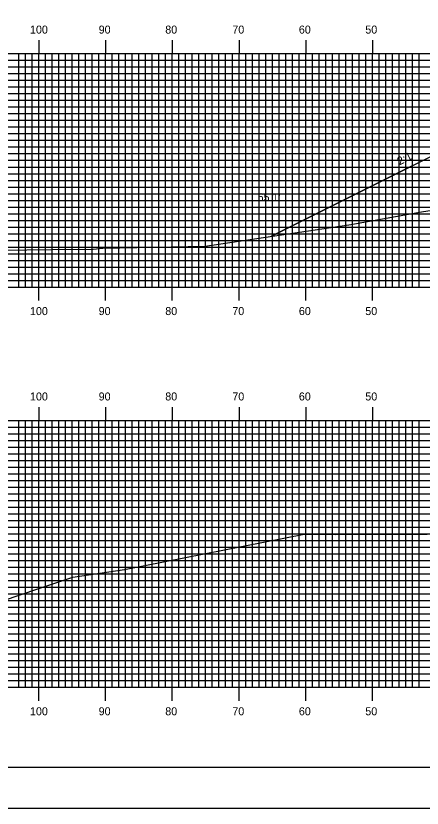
# Model space of a CAD drawing. Extents: x 1755888 to 1756232, y 442591 to 442811.
# Drawn here: x 1755950.6 to 1756011.5, y 442590.5 to 442709.3 of the extents above; entities that cross this region are included whole.
import ezdxf

# ---------------------------------------------------------------- set-up
doc = ezdxf.new("R2010")
doc.units = 0
for name, color, linetype in [('ANNOTATION', 7, 'Continuous'), ('BORDER', 7, 'Continuous'), ('D_Roadway_Centerline', 7, 'Continuous'), ('D_Roadway_SlopeLines', 7, 'Continuous'), ('D_Text_Standard', 7, 'Continuous'), ('H_V ANNOTATION', 7, 'Continuous'), ('MAJOR', 7, 'Continuous'), ('MINOR', 7, 'Continuous'), ('PLOT BOUNDARY', 7, 'Continuous'), ('S_Roadway_Centerline', 7, 'Continuous')]:
    doc.layers.add(name, color=color, linetype=linetype)

msp = doc.modelspace()

# ---------------------------------------------------------------- linework, layer by layer
at = {"layer": 'BORDER'}
msp.add_lwpolyline([(1755904.46, 442596.67), (1756224.46, 442596.67), (1756224.46, 442806.67), (1755904.46, 442806.67)], close=True, dxfattribs=at)
at = {"layer": 'D_Roadway_Centerline'}
msp.add_lwpolyline([(1755988.92, 442676.28), (1756026.31, 442694.97), (1756031.06, 442697.35), (1756034.06, 442697.47), (1756042.06, 442697.79), (1756054.06, 442698.03), (1756066.06, 442697.79), (1756078.06, 442697.31), (1756093.72, 442696.69), (1756103.15, 442694.07), (1756119.31, 442689.58)], dxfattribs=at)
at = {"layer": 'D_Roadway_SlopeLines'}
msp.add_lwpolyline([(1756031.06, 442697.35), (1755988.92, 442676.28)], dxfattribs=at)
at = {"layer": 'MAJOR'}
for p, q in [((1755954.06, 442705.67), (1755954.06, 442703.67)), ((1755964.06, 442705.67), (1755964.06, 442703.67)), ((1755974.06, 442705.67), (1755974.06, 442703.67)), ((1755984.06, 442705.67), (1755984.06, 442703.67)), ((1755994.06, 442705.67), (1755994.06, 442703.67)), ((1756004.06, 442705.67), (1756004.06, 442703.67)), ((1755914.06, 442703.67), (1756194.06, 442703.67)), ((1755914.06, 442703.67), (1756194.06, 442703.67)), ((1755954.06, 442668.67), (1755954.06, 442703.67)), ((1755964.06, 442668.67), (1755964.06, 442703.67)), ((1755974.06, 442668.67), (1755974.06, 442703.67)), ((1755984.06, 442668.67), (1755984.06, 442703.67)), ((1755994.06, 442668.67), (1755994.06, 442703.67)), ((1756004.06, 442668.67), (1756004.06, 442703.67)), ((1755914.06, 442698.67), (1756194.06, 442698.67)), ((1755914.06, 442693.67), (1756194.06, 442693.67)), ((1755914.06, 442688.67), (1756194.06, 442688.67)), ((1755914.06, 442683.67), (1756194.06, 442683.67)), ((1755914.06, 442678.67), (1756194.06, 442678.67)), ((1755914.06, 442673.67), (1756194.06, 442673.67)), ((1755914.06, 442668.67), (1756194.06, 442668.67)), ((1755914.06, 442668.67), (1756194.06, 442668.67)), ((1755954.06, 442666.66), (1755954.06, 442668.67)), ((1755964.06, 442666.66), (1755964.06, 442668.67)), ((1755974.06, 442666.66), (1755974.06, 442668.67)), ((1755984.06, 442666.66), (1755984.06, 442668.67)), ((1755994.06, 442666.66), (1755994.06, 442668.67)), ((1756004.06, 442666.66), (1756004.06, 442668.67)), ((1755954.06, 442650.67), (1755954.06, 442648.67)), ((1755964.06, 442650.67), (1755964.06, 442648.67)), ((1755974.06, 442650.67), (1755974.06, 442648.67)), ((1755984.06, 442650.67), (1755984.06, 442648.67)), ((1755994.06, 442650.67), (1755994.06, 442648.67)), ((1756004.06, 442650.67), (1756004.06, 442648.67)), ((1755914.06, 442648.67), (1756194.06, 442648.67)), ((1755914.06, 442648.67), (1756194.06, 442648.67)), ((1755954.06, 442608.67), (1755954.06, 442648.67)), ((1755964.06, 442608.67), (1755964.06, 442648.67)), ((1755974.06, 442608.67), (1755974.06, 442648.67)), ((1755984.06, 442608.67), (1755984.06, 442648.67)), ((1755994.06, 442608.67), (1755994.06, 442648.67)), ((1756004.06, 442608.67), (1756004.06, 442648.67)), ((1755914.06, 442643.67), (1756194.06, 442643.67)), ((1755914.06, 442638.67), (1756194.06, 442638.67)), ((1755914.06, 442633.67), (1756194.06, 442633.67)), ((1755914.06, 442628.67), (1756194.06, 442628.67)), ((1755914.06, 442623.67), (1756194.06, 442623.67)), ((1755914.06, 442618.67), (1756194.06, 442618.67)), ((1755914.06, 442613.67), (1756194.06, 442613.67)), ((1755914.06, 442608.67), (1756194.06, 442608.67)), ((1755914.06, 442608.67), (1756194.06, 442608.67)), ((1755954.06, 442606.66), (1755954.06, 442608.67)), ((1755964.06, 442606.66), (1755964.06, 442608.67)), ((1755974.06, 442606.66), (1755974.06, 442608.67)), ((1755984.06, 442606.66), (1755984.06, 442608.67)), ((1755994.06, 442606.66), (1755994.06, 442608.67)), ((1756004.06, 442606.66), (1756004.06, 442608.67))]:
    msp.add_line(p, q, dxfattribs=at)
at = {"layer": 'MINOR'}
for p, q in [((1755914.06, 442702.67), (1756194.06, 442702.67)), ((1755951.06, 442668.67), (1755951.06, 442703.67)), ((1755952.06, 442668.67), (1755952.06, 442703.67)), ((1755953.06, 442668.67), (1755953.06, 442703.67)), ((1755955.06, 442668.67), (1755955.06, 442703.67)), ((1755956.06, 442668.67), (1755956.06, 442703.67)), ((1755957.06, 442668.67), (1755957.06, 442703.67)), ((1755958.06, 442668.67), (1755958.06, 442703.67)), ((1755959.06, 442668.67), (1755959.06, 442703.67)), ((1755960.06, 442668.67), (1755960.06, 442703.67)), ((1755961.06, 442668.67), (1755961.06, 442703.67)), ((1755962.06, 442668.67), (1755962.06, 442703.67)), ((1755963.06, 442668.67), (1755963.06, 442703.67)), ((1755965.06, 442668.67), (1755965.06, 442703.67)), ((1755966.06, 442668.67), (1755966.06, 442703.67)), ((1755967.06, 442668.67), (1755967.06, 442703.67)), ((1755968.06, 442668.67), (1755968.06, 442703.67)), ((1755969.06, 442668.67), (1755969.06, 442703.67)), ((1755970.06, 442668.67), (1755970.06, 442703.67)), ((1755971.06, 442668.67), (1755971.06, 442703.67)), ((1755972.06, 442668.67), (1755972.06, 442703.67)), ((1755973.06, 442668.67), (1755973.06, 442703.67)), ((1755975.06, 442668.67), (1755975.06, 442703.67)), ((1755976.06, 442668.67), (1755976.06, 442703.67)), ((1755977.06, 442668.67), (1755977.06, 442703.67)), ((1755978.06, 442668.67), (1755978.06, 442703.67)), ((1755979.06, 442668.67), (1755979.06, 442703.67)), ((1755980.06, 442668.67), (1755980.06, 442703.67)), ((1755981.06, 442668.67), (1755981.06, 442703.67)), ((1755982.06, 442668.67), (1755982.06, 442703.67)), ((1755983.06, 442668.67), (1755983.06, 442703.67)), ((1755985.06, 442668.67), (1755985.06, 442703.67)), ((1755986.06, 442668.67), (1755986.06, 442703.67)), ((1755987.06, 442668.67), (1755987.06, 442703.67)), ((1755988.06, 442668.67), (1755988.06, 442703.67)), ((1755989.06, 442668.67), (1755989.06, 442703.67)), ((1755990.06, 442668.67), (1755990.06, 442703.67)), ((1755991.06, 442668.67), (1755991.06, 442703.67)), ((1755992.06, 442668.67), (1755992.06, 442703.67)), ((1755993.06, 442668.67), (1755993.06, 442703.67)), ((1755995.06, 442668.67), (1755995.06, 442703.67)), ((1755996.06, 442668.67), (1755996.06, 442703.67)), ((1755997.06, 442668.67), (1755997.06, 442703.67)), ((1755998.06, 442668.67), (1755998.06, 442703.67)), ((1755999.06, 442668.67), (1755999.06, 442703.67)), ((1756000.06, 442668.67), (1756000.06, 442703.67)), ((1756001.06, 442668.67), (1756001.06, 442703.67)), ((1756002.06, 442668.67), (1756002.06, 442703.67)), ((1756003.06, 442668.67), (1756003.06, 442703.67)), ((1756005.06, 442668.67), (1756005.06, 442703.67)), ((1756006.06, 442668.67), (1756006.06, 442703.67)), ((1756007.06, 442668.67), (1756007.06, 442703.67)), ((1756008.06, 442668.67), (1756008.06, 442703.67)), ((1756009.06, 442668.67), (1756009.06, 442703.67)), ((1756010.06, 442668.67), (1756010.06, 442703.67)), ((1756011.06, 442668.67), (1756011.06, 442703.67)), ((1755914.06, 442701.67), (1756194.06, 442701.67)), ((1755914.06, 442700.67), (1756194.06, 442700.67)), ((1755914.06, 442699.67), (1756194.06, 442699.67)), ((1755914.06, 442697.67), (1756194.06, 442697.67)), ((1755914.06, 442696.67), (1756194.06, 442696.67)), ((1755914.06, 442695.67), (1756194.06, 442695.67)), ((1755914.06, 442694.67), (1756194.06, 442694.67)), ((1755914.06, 442692.67), (1756194.06, 442692.67)), ((1755914.06, 442691.67), (1756194.06, 442691.67)), ((1755914.06, 442690.67), (1756194.06, 442690.67)), ((1755914.06, 442689.67), (1756194.06, 442689.67)), ((1755914.06, 442687.67), (1756194.06, 442687.67)), ((1755914.06, 442686.67), (1756194.06, 442686.67)), ((1755914.06, 442685.67), (1756194.06, 442685.67)), ((1755914.06, 442684.67), (1756194.06, 442684.67)), ((1755914.06, 442682.67), (1756194.06, 442682.67)), ((1755914.06, 442681.67), (1756194.06, 442681.67)), ((1755914.06, 442680.67), (1756194.06, 442680.67)), ((1755914.06, 442679.67), (1756194.06, 442679.67)), ((1755914.06, 442677.67), (1756194.06, 442677.67)), ((1755914.06, 442676.67), (1756194.06, 442676.67)), ((1755914.06, 442675.67), (1756194.06, 442675.67)), ((1755914.06, 442674.67), (1756194.06, 442674.67)), ((1755914.06, 442672.67), (1756194.06, 442672.67)), ((1755914.06, 442671.67), (1756194.06, 442671.67)), ((1755914.06, 442670.67), (1756194.06, 442670.67)), ((1755914.06, 442669.67), (1756194.06, 442669.67)), ((1755951.06, 442608.67), (1755951.06, 442648.67)), ((1755952.06, 442608.67), (1755952.06, 442648.67)), ((1755953.06, 442608.67), (1755953.06, 442648.67)), ((1755955.06, 442608.67), (1755955.06, 442648.67)), ((1755956.06, 442608.67), (1755956.06, 442648.67)), ((1755957.06, 442608.67), (1755957.06, 442648.67)), ((1755958.06, 442608.67), (1755958.06, 442648.67)), ((1755959.06, 442608.67), (1755959.06, 442648.67)), ((1755960.06, 442608.67), (1755960.06, 442648.67)), ((1755961.06, 442608.67), (1755961.06, 442648.67)), ((1755962.06, 442608.67), (1755962.06, 442648.67)), ((1755963.06, 442608.67), (1755963.06, 442648.67)), ((1755965.06, 442608.67), (1755965.06, 442648.67)), ((1755966.06, 442608.67), (1755966.06, 442648.67)), ((1755967.06, 442608.67), (1755967.06, 442648.67)), ((1755968.06, 442608.67), (1755968.06, 442648.67)), ((1755969.06, 442608.67), (1755969.06, 442648.67)), ((1755970.06, 442608.67), (1755970.06, 442648.67)), ((1755971.06, 442608.67), (1755971.06, 442648.67)), ((1755972.06, 442608.67), (1755972.06, 442648.67)), ((1755973.06, 442608.67), (1755973.06, 442648.67)), ((1755975.06, 442608.67), (1755975.06, 442648.67)), ((1755976.06, 442608.67), (1755976.06, 442648.67)), ((1755977.06, 442608.67), (1755977.06, 442648.67)), ((1755978.06, 442608.67), (1755978.06, 442648.67)), ((1755979.06, 442608.67), (1755979.06, 442648.67)), ((1755980.06, 442608.67), (1755980.06, 442648.67)), ((1755981.06, 442608.67), (1755981.06, 442648.67)), ((1755982.06, 442608.67), (1755982.06, 442648.67)), ((1755983.06, 442608.67), (1755983.06, 442648.67)), ((1755985.06, 442608.67), (1755985.06, 442648.67)), ((1755986.06, 442608.67), (1755986.06, 442648.67)), ((1755987.06, 442608.67), (1755987.06, 442648.67)), ((1755988.06, 442608.67), (1755988.06, 442648.67)), ((1755989.06, 442608.67), (1755989.06, 442648.67)), ((1755990.06, 442608.67), (1755990.06, 442648.67)), ((1755991.06, 442608.67), (1755991.06, 442648.67)), ((1755992.06, 442608.67), (1755992.06, 442648.67)), ((1755993.06, 442608.67), (1755993.06, 442648.67)), ((1755995.06, 442608.67), (1755995.06, 442648.67)), ((1755996.06, 442608.67), (1755996.06, 442648.67)), ((1755997.06, 442608.67), (1755997.06, 442648.67)), ((1755998.06, 442608.67), (1755998.06, 442648.67)), ((1755999.06, 442608.67), (1755999.06, 442648.67)), ((1756000.06, 442608.67), (1756000.06, 442648.67)), ((1756001.06, 442608.67), (1756001.06, 442648.67)), ((1756002.06, 442608.67), (1756002.06, 442648.67)), ((1756003.06, 442608.67), (1756003.06, 442648.67)), ((1756005.06, 442608.67), (1756005.06, 442648.67)), ((1756006.06, 442608.67), (1756006.06, 442648.67)), ((1756007.06, 442608.67), (1756007.06, 442648.67)), ((1756008.06, 442608.67), (1756008.06, 442648.67)), ((1756009.06, 442608.67), (1756009.06, 442648.67)), ((1756010.06, 442608.67), (1756010.06, 442648.67)), ((1756011.06, 442608.67), (1756011.06, 442648.67)), ((1755914.06, 442647.67), (1756194.06, 442647.67)), ((1755914.06, 442646.67), (1756194.06, 442646.67)), ((1755914.06, 442645.67), (1756194.06, 442645.67)), ((1755914.06, 442644.67), (1756194.06, 442644.67)), ((1755914.06, 442642.67), (1756194.06, 442642.67)), ((1755914.06, 442641.67), (1756194.06, 442641.67)), ((1755914.06, 442640.67), (1756194.06, 442640.67)), ((1755914.06, 442639.67), (1756194.06, 442639.67)), ((1755914.06, 442637.67), (1756194.06, 442637.67)), ((1755914.06, 442636.67), (1756194.06, 442636.67)), ((1755914.06, 442635.67), (1756194.06, 442635.67)), ((1755914.06, 442634.67), (1756194.06, 442634.67)), ((1755914.06, 442632.67), (1756194.06, 442632.67)), ((1755914.06, 442631.67), (1756194.06, 442631.67)), ((1755914.06, 442630.67), (1756194.06, 442630.67)), ((1755914.06, 442629.67), (1756194.06, 442629.67)), ((1755914.06, 442627.67), (1756194.06, 442627.67)), ((1755914.06, 442626.67), (1756194.06, 442626.67)), ((1755914.06, 442625.67), (1756194.06, 442625.67)), ((1755914.06, 442624.67), (1756194.06, 442624.67)), ((1755914.06, 442622.67), (1756194.06, 442622.67)), ((1755914.06, 442621.67), (1756194.06, 442621.67)), ((1755914.06, 442620.67), (1756194.06, 442620.67)), ((1755914.06, 442619.67), (1756194.06, 442619.67)), ((1755914.06, 442617.67), (1756194.06, 442617.67)), ((1755914.06, 442616.67), (1756194.06, 442616.67)), ((1755914.06, 442615.67), (1756194.06, 442615.67)), ((1755914.06, 442614.67), (1756194.06, 442614.67)), ((1755914.06, 442612.67), (1756194.06, 442612.67)), ((1755914.06, 442611.67), (1756194.06, 442611.67)), ((1755914.06, 442610.67), (1756194.06, 442610.67)), ((1755914.06, 442609.67), (1756194.06, 442609.67))]:
    msp.add_line(p, q, dxfattribs=at)
at = {"layer": 'PLOT BOUNDARY'}
msp.add_lwpolyline([(1755888.27, 442590.55), (1756228.27, 442590.55), (1756228.27, 442810.55), (1755888.27, 442810.55)], close=True, dxfattribs=at)
at = {"layer": 'S_Roadway_Centerline'}
for points in [[(1755914.06, 442673.7), (1755921.43, 442673.85), (1755956.11, 442674.32), (1755962.18, 442674.36), (1755963.67, 442674.48), (1755979, 442674.79), (1756000.51, 442678.02), (1756003.6, 442678.56), (1756011.42, 442679.93), (1756013.98, 442680.37)], [(1755914.06, 442615.49), (1755925.39, 442615.38), (1755932.41, 442615.46), (1755943.1, 442619.79), (1755954.08, 442623.5), (1755959.17, 442625.2), (1755966.89, 442626.32), (1755993.82, 442631.63), (1755998.58, 442631.59), (1756012.24, 442631.63)]]:
    msp.add_lwpolyline(points, dxfattribs=at)

# ---------------------------------------------------------------- texts
at = {"layer": 'ANNOTATION'}
msp.add_text('2:1', height=1.2, rotation=26.5651, dxfattribs=at).set_placement((1756008.13, 442686.92))
at = {"layer": 'D_Text_Standard'}
msp.add_text("65.1'", height=1.2, dxfattribs=at).set_placement((1755986.85, 442681.54))
at = {"layer": 'H_V ANNOTATION'}
for s, p in [('100', (1755952.74, 442706.67)), ('90', (1755963.03, 442706.67)), ('80', (1755973.01, 442706.67)), ('70', (1755983.06, 442706.67)), ('60', (1755993.03, 442706.67)), ('50', (1756002.99, 442706.67)), ('100', (1755952.74, 442664.47)), ('90', (1755963.03, 442664.47)), ('80', (1755973.01, 442664.47)), ('70', (1755983.06, 442664.47)), ('60', (1755993.03, 442664.47)), ('50', (1756002.99, 442664.47)), ('100', (1755952.74, 442651.67)), ('90', (1755963.03, 442651.67)), ('80', (1755973.01, 442651.67)), ('70', (1755983.06, 442651.67)), ('60', (1755993.03, 442651.67)), ('50', (1756002.99, 442651.67)), ('100', (1755952.74, 442604.47)), ('90', (1755963.03, 442604.47)), ('80', (1755973.01, 442604.47)), ('70', (1755983.06, 442604.47)), ('60', (1755993.03, 442604.47)), ('50', (1756002.99, 442604.47))]:
    msp.add_text(s, height=1.2, dxfattribs=at).set_placement(p)

doc.saveas('drawing.dxf')
